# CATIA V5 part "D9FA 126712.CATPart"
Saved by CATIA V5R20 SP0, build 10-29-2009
Part number: D9FA 126712
Revision: ANY
Definition: UNKNOWN
Nomenclature: D9FA 126712
Source: Unknown
Bounding box of the stored display mesh (mm): x -5.85 to 5.85, y -10 to 10, z -6 to 6
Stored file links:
  C:\Users\Utente\Desktop\IO LAVORO\3D X SITO CF\CUMSA\3D files FA\FA 126712-21\D9FA 126712.CATPart
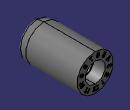
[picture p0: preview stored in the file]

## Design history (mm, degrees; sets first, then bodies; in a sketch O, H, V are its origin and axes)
Body1 "Cortar-Extruir5" (main body)
  Solid1: solid without history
